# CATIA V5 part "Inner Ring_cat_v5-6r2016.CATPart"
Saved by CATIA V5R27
Part number: Inner Ring
Bounding box of the stored display mesh (mm): x -69.995 to 69.995, y 0 to 50, z -69.995 to 69.995
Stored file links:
  E:\_Deepak\2017_Deepak\CATIA\Resources\Tutorial Files\Tutorials\c16_catia_v5_6r2016_tut\Bearing\Inner Ring_cat_v5-6r2016.CATPart
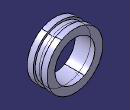
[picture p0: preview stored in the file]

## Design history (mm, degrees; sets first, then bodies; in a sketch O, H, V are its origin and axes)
Body1 (main body)
  Sketch1 on yz-plane, origin (0, 0, 0), H (0, 1, 0), V (0, 0, 1)
    point P1 (0, 50)
    line L1 (0, 50) -> (0, 70)
    line L2 (0, 70) -> (15, 70)
    line L3 (15, 70) -> (15, 65)
    line L4 (15, 65) -> (35, 65)
    line L5 (35, 65) -> (35, 70)
    point P6 (35, 70)
    line L6 (35, 70) -> (50, 70)
    line L7 (50, 70) -> (50, 50)
    line L8 (50, 50) -> (0, 50)
    distance L8 H = 50
    length L8 = 50
    length L6 = 15
    length L2 = 15
    length L7 = 20
    distance L8 L4 = 15
    coincidence: P1 V, P6 L2
    vertical: L1 V, L3 V, L5 V, L7 V
    horizontal: L2 H, L4 H, L6 H, L8 H
  Shaft1: profile Sketch1, axis Sketch1.H, angle 360
  Plane1: type Offset, RefPlane face of Shaft1 from Sketch1.L3, Offset 10, reversed
  Sketch2 on Plane1, origin (0, 25, 0), H (1, 0, 0), V (0, 0, 1)
    projected circle E1 centre (0, 0) radius 65 from edge [face of Shaft1 from Sketch1.L4 | face of Shaft1 from Sketch1.L5]
  Point1: type OnCurve, Support Sketch2, RefPoint {extremum Reference Sketch2, Direction (1, 2, 3)}, Length 192.617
